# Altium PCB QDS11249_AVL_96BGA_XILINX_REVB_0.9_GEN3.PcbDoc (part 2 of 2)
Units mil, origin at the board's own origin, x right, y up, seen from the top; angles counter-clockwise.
Board outline 3000.03 x 2525.24 mil, 10 copper layers (Top Layer, GND1 - COMMON, INT1, PWR1 - VCC, GND2 - VSS, PWR2 - VCC/VCCIO-EXIT, GND3 - VSSIO, PWR3 - VCCIO, GND4 - COMMON, Bottom Layer), stack 67.702 mil thick; 142 components, 64 nets, 703 pads, 440 vias.
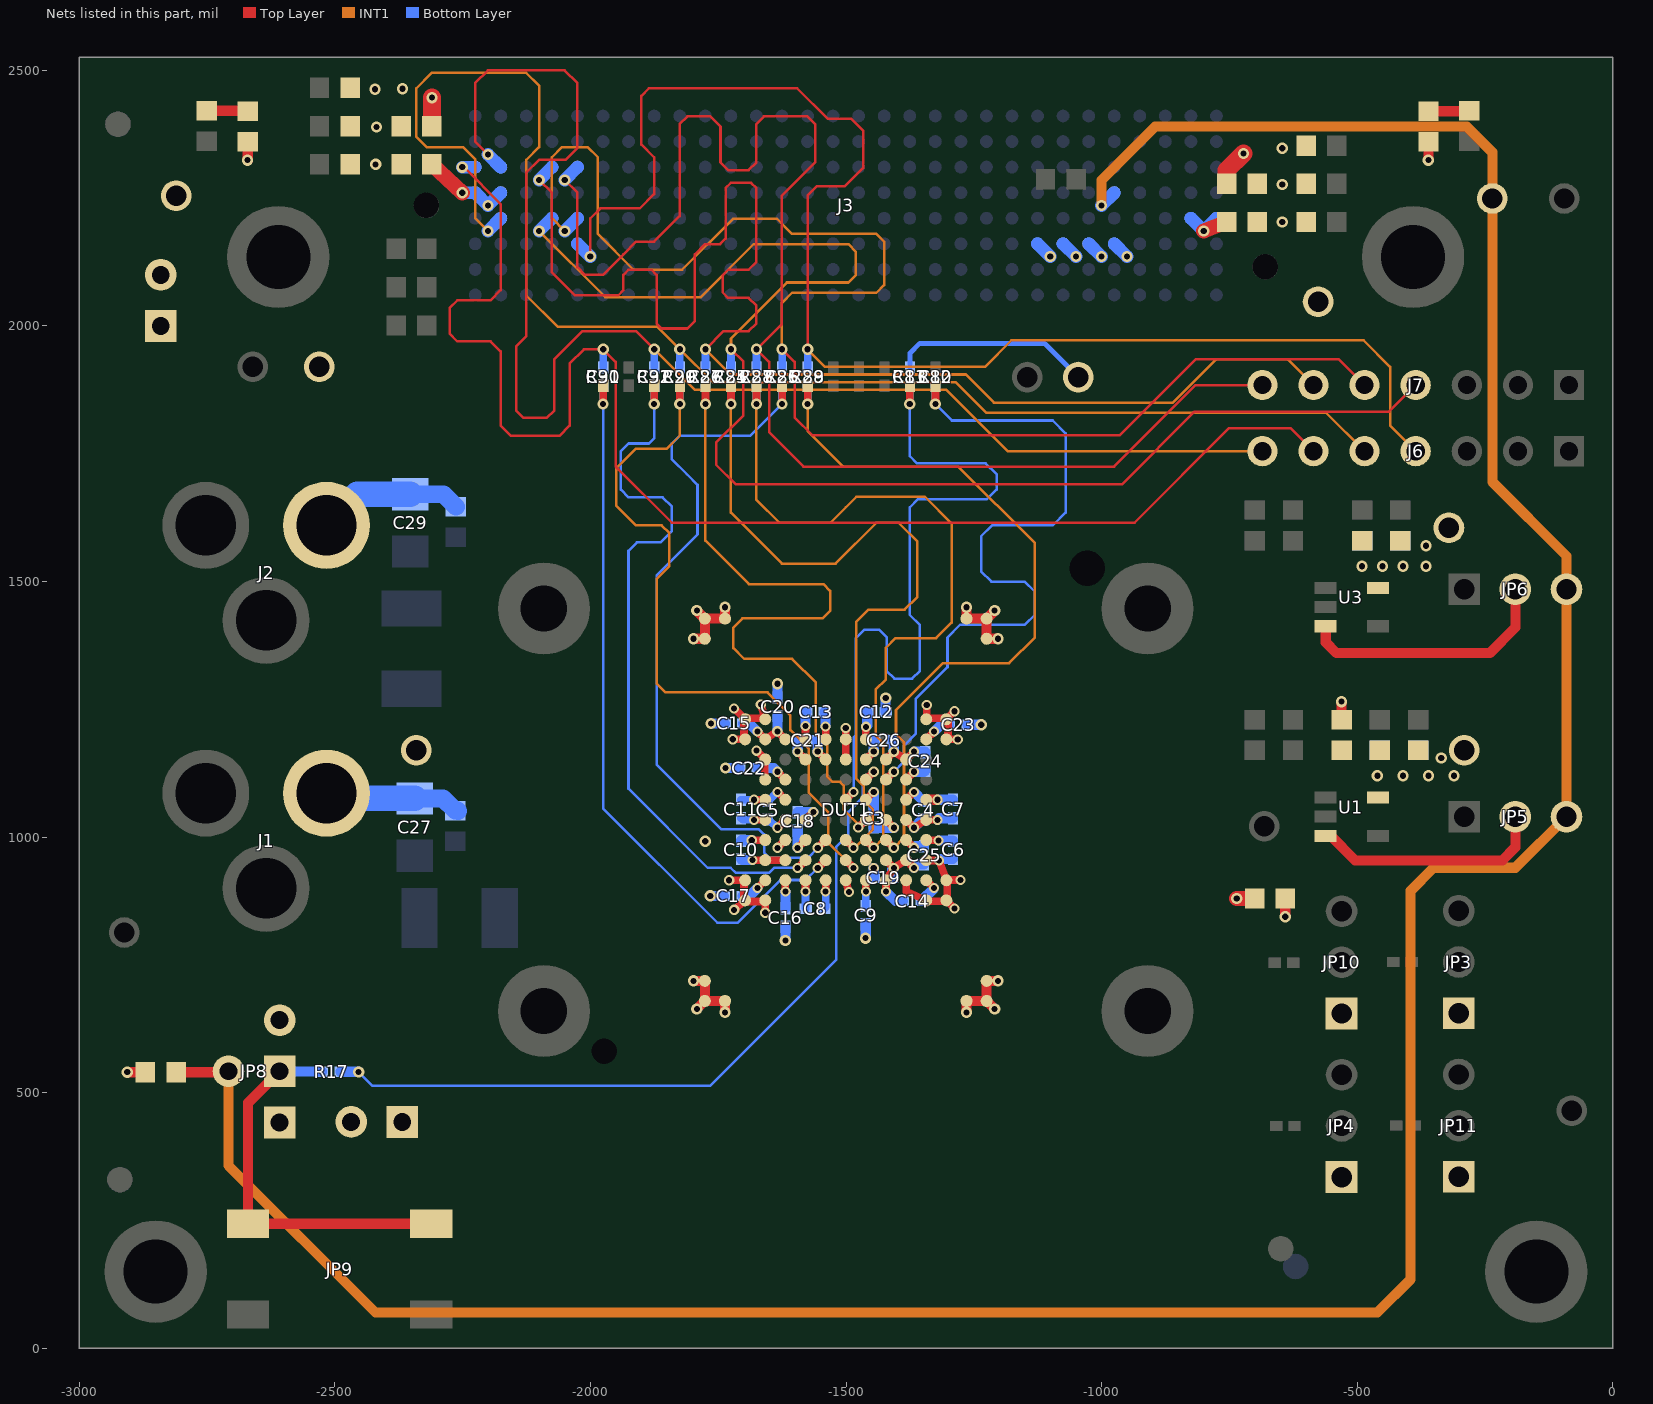
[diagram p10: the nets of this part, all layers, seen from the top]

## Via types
v1: diameter 22, hole 12, Top Layer to Bottom Layer, tented both sides, 368 vias
v2: diameter 20, hole 12, Top Layer to Bottom Layer, tented both sides, 72 vias

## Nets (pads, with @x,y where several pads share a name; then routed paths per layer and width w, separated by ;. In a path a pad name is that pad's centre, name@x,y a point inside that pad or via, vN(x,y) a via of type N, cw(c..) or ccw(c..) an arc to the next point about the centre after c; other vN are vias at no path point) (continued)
INT1#_1: C80.2 DUT1.J10 R12.2 | length 1440.9
  Top Layer w15: DUT1.J10@-1421.76,1112.47 v2(-1406.4,1127.83) ; v1@-1325.02,1847.46 C80.2@-1325.02,1882.86
  Bottom Layer w5: v2(-1406.4,1127.83) -1386.76,1147.47 -1386.76,1178.7 -1363.14,1202.33 -1363.14,1270.72 -1301.5,1332.36 -1301.5,1390.54 -1276.5,1415.54 -1149.92,1415.54 -1130.51,1434.95 -1130.51,1479.95 -1150.51,1499.95 -1215.51,1499.95 -1235.51,1519.95 -1235.51,1588.57 -1214.13,1609.95 -1095.51,1609.95 -1070.51,1634.95 -1070.51,1789.95 -1095.51,1814.95 -1293.01,1814.95 v1(-1325.27,1847.21)
  Bottom Layer w15: v1(-1325.27,1847.21) R12.2@-1325.27,1882.61
INT2#: INT2#.1 R13.1 | length 392.5
  Bottom Layer w10: R13.1@-1375.02,1918.86 -1375.02,1946.45 -1355.51,1965.95 -1111.51,1965.95 INT2#.1@-1045.51,1899.95
INT2#_1: C81.2 DUT1.K8 R13.2 | length 1440.7
  Top Layer w15: DUT1.K8@-1500.5,1073.1 v2(-1485.14,1088.46) ; v1@-1375.02,1847.46 C81.2@-1375.02,1882.86
  Bottom Layer w5: v2(-1485.14,1088.46) -1485.14,1194.9 -1481.24,1198.81 -1481.24,1388.72 -1464.42,1405.54 -1434.8,1405.54 -1420.51,1391.26 -1420.51,1324.95 -1405.51,1309.95 -1370.51,1309.95 -1355.51,1324.95 -1355.51,1414.95 -1375.27,1434.7 -1375.27,1645.2 -1359.33,1661.13 -1224.33,1661.13 -1205.51,1679.95 -1205.51,1709.95 -1226.7,1731.13 -1361.21,1731.13 -1375.27,1745.19 v1(-1375.27,1847.21)
  Bottom Layer w15: v1(-1375.27,1847.21) R13.2@-1375.27,1882.61
IO0: J3.E4 J7.4 R24.1 | length 2877
  Top Layer w5: v1(-1725.02,1954.26) -1700.95,1930.19 -1700.95,1824.95 -1753.99,1771.91 -1753.99,1728.43 -1715.51,1689.95 -1625.51,1689.95 ; -1624.34,1689.95 -960.51,1689.95 -818.12,1832.34 -437.4,1832.34 J7.4@-385.51,1884.22
  INT1 w5: v1(-2100.33,2185.7) -1971.01,2056.38 -1784.09,2056.38 -1680.51,2159.95 -1495.51,2159.95 -1480.51,2144.95 -1480.51,2099.95 -1495.51,2084.95 -1615.51,2084.95 -1725.02,1975.45 v1(-1725.02,1954.26)
  Bottom Layer w15: R24.1@-1725.02,1918.86 v1(-1725.02,1954.26)
  Bottom Layer w25: v1(-2100.33,2185.7) J3.E4@-2075.29,2210.66
IO0_1: C85.2 DUT1.M8 R24.2 | length 1479.7
  Top Layer w15: v1(-1725.02,1847.46) C85.2@-1725.02,1882.86 ; DUT1.M8@-1500.5,994.36 v2(-1485.14,979)
  INT1 w5: v1@-1725.27,1847.46 -1725.27,1634.7 -1625.51,1534.95 -1520.51,1534.95 -1440.51,1614.95 -1396.99,1614.95 -1360.51,1578.48 -1360.51,1469.95 -1385.51,1444.95 -1456.07,1444.95 -1480.02,1421.01 -1480.02,1114.86 -1465.51,1100.36 -1465.51,1071.6 -1447.58,1053.66 -1447.58,1015.21 -1483.79,979 v2(-1485.14,979)
  Bottom Layer w15: v1(-1725.02,1847.46) R24.2@-1725.02,1882.86
IO1: J3.E5 J7.5 R25.1 | length 2876.6
  Top Layer w5: v1(-1625.02,1954.26) -1600.46,1929.7 -1600.46,1820.58 -1566.07,1786.19 -964.28,1786.19 -815.28,1935.19 -536.48,1935.19 J7.5@-485.51,1884.22
  INT1 w5: v1(-2050.29,2185.66) -2075.51,2210.88 -2075.51,2329.95 -2055.51,2349.95 -2005.51,2349.95 -1985.51,2329.95 -1985.51,2179.95 -1915.51,2109.95 -1820.51,2109.95 -1720.51,2209.95 -1635.51,2209.95 -1605.51,2179.95 -1440.51,2179.95 -1425.51,2164.95 -1425.51,2079.95 -1440.51,2064.95 -1605.51,2064.95 -1625.51,2044.95 v1@-1625.51,1954.95 ; v1(-1625.02,1954.26) v1@-1624.92,1954.36
  Bottom Layer w15: R25.1@-1625.02,1918.86 v1(-1625.02,1954.26)
  Bottom Layer w25: v1@-2050.25,2185.62 J3.E5@-2025.25,2210.62
IO1_1: C86.2 DUT1.M7 R25.2 | length 1441.3
  Top Layer w15: v1@-1625.02,1847.46 C86.2@-1625.02,1882.86 ; v2(-1555.24,979) DUT1.M7@-1539.87,994.36
  Bottom Layer w5: v1(-1625.27,1847.21) -1687.52,1784.95 -1825.51,1784.95 -1840.51,1769.95 -1840.51,1738.95 -1811.51,1709.95 -1790.51,1688.95 -1790.51,1591.95 -1870.55,1511.92 -1870.55,1141.99 -1744.24,1015.67 -1670.91,1015.67 -1660.35,1005.12 -1660.35,969.79 -1650.01,959.45 -1574.79,959.45 v2(-1555.24,979)
  Bottom Layer w15: v1(-1625.27,1847.21) R25.2@-1625.27,1882.61
IO2: J3.C4 J7.6 R26.1 | length 2854.2
  Top Layer w5: v1(-2100.24,2285.66) -2075.5,2260.92 -2075.5,2104.94 -2030.51,2059.95 -1945.51,2059.95 -1935.51,2069.95 -1935.51,2099.95 -1925.51,2109.95 -1880.51,2109.95 -1870.51,2099.95 -1870.51,2004.95 -1860.51,1994.95 -1810.51,1994.95 -1795.51,2009.95 -1795.51,2139.95 -1775.51,2159.95 -1746.51,2159.95 -1735.51,2170.95 -1735.51,2269.95 -1725.51,2279.95 -1685.51,2279.95 -1675.51,2269.95 -1675.51,2124.95 -1690.51,2109.95 -1730.51,2109.95 -1741.47,2099 -1741.47,2065.91 -1730.51,2054.95 -1690.51,2054.95 -1675.51,2039.95 -1675.51,2004.95 -1690.51,1989.95 -1739.32,1989.95 v1(-1775.02,1954.26)
  INT1 w5: v1(-1775.02,1954.26) -1725.71,1904.95 -1265.51,1904.95 -1210.51,1849.95 -860.51,1849.95 -775.51,1934.95 -636.24,1934.95 J7.6@-585.51,1884.22
  Bottom Layer w15: R26.1@-1775.02,1918.86 v1(-1775.02,1954.26)
  Bottom Layer w25: v1@-2100.2,2285.62 J3.C4@-2075.2,2310.62
IO2_1: C87.2 DUT1.L9 R26.2 | length 1441
  Top Layer w15: v1(-1775.02,1847.46) C87.2@-1775.02,1882.86 ; v2(-1476.12,1018.75) DUT1.L9@-1460.76,1034.11
  INT1 w5: v1@-1775.27,1847.46 -1775.27,1580.26 -1689.83,1494.83 -1543.89,1494.83 -1530.9,1481.83 -1530.9,1442.54 -1545.59,1427.85 -1702.62,1427.85 -1720.51,1409.95 -1720.51,1369.95 -1699.1,1348.54 -1605.5,1348.54 -1559.02,1302.07 -1559.02,1201.86 -1536.97,1179.81 -1536.97,1118.92 -1526,1107.95 -1511.74,1107.95 -1504.83,1101.05 -1504.83,1092.09 -1504.83,1053.99 v2@-1472.85,1022.01
  Bottom Layer w10: v1(-1775.02,1847.46) R26.2@-1775.02,1882.86
IO3: J3.C5 J7.7 R27.1 | length 2854.1
  Top Layer w5: v1(-2050.24,2285.66) -2025.5,2260.92 -2025.5,2114.94 -2010.51,2099.95 -1975.51,2099.95 -1935.51,2139.95 -1910.51,2164.95 -1875.51,2164.95 -1825.51,2214.95 -1825.51,2394.95 -1810.51,2409.95 -1765.51,2409.95 -1745.51,2389.95 -1745.51,2319.95 -1730.51,2304.95 -1690.51,2304.95 -1675.51,2319.95 -1675.51,2394.95 -1660.51,2409.95 -1575.51,2409.95 -1560.51,2394.95 -1560.51,2319.95 -1625.51,2254.95 -1625.51,2003.76 v1(-1675.02,1954.26) -1650.51,1929.76 -1650.51,1792.21 -1583.26,1724.95 -975.51,1724.95 -816.24,1884.22 J7.7@-685.51,1884.22
  Bottom Layer w15: R27.1@-1675.02,1918.86 v1(-1675.02,1954.26)
  Bottom Layer w25: v1@-2050.2,2285.62 J3.C5@-2025.2,2310.62
IO3_1: C88.2 DUT1.M9 R27.2 | length 1480
  Top Layer w15: v1(-1675.02,1847.46) C88.2@-1675.02,1882.86 ; DUT1.M9@-1461.13,994.36 v2(-1445.77,979)
  INT1 w5: v1@-1675.27,1847.46 -1675.27,1659.7 -1630.51,1614.95 -1530.51,1614.95 -1500.51,1644.95 -1479.62,1665.84 -1345.79,1665.84 -1293.47,1613.52 -1293.47,1419.55 -1323.93,1389.09 -1403.32,1389.09 -1421.96,1370.45 -1421.96,1308.51 -1442.02,1288.45 -1442.02,1198.86 -1426.87,1183.71 -1426.87,997.91 v2(-1445.77,979)
  Bottom Layer w15: v1(-1675.02,1847.46) R27.2@-1675.02,1882.86
IO4: J3.F5 J6.4 R28.1 | length 2854.1
  Top Layer w5: v1(-2000.33,2135.7) -2000.33,2210.14 -1980.51,2229.95 -1903.51,2229.95 -1875.51,2257.95 -1875.51,2329.95 -1900.51,2354.95 -1900.51,2449.95 -1885.51,2464.95 -1595.51,2464.95 -1535.51,2404.95 -1489.51,2404.95 -1466.51,2381.95 -1466.51,2308.95 -1502.51,2272.95 -1557.51,2272.95 -1575.02,2255.45 v1(-1575.02,1954.26)
  INT1 w5: v1(-1575.02,1954.26) -1540.71,1919.95 -1228.51,1919.95 -1176.51,1971.95 -487.51,1971.95 -435.51,1919.95 -435.51,1804.95 J6.4@-385.51,1754.95
  Bottom Layer w15: R28.1@-1575.02,1918.86 v1(-1575.02,1954.26)
  Bottom Layer w25: J3.F5@-2025.29,2160.66 v1(-2000.33,2135.7) v1(-2000.33,2135.7)
IO4_1: C89.2 DUT1.M10 R28.2 | length 1479.8
  Top Layer w15: v1(-1575.02,1847.46) C89.2@-1575.02,1882.86 ; DUT1.M10@-1421.76,994.36 v2(-1406.4,979)
  INT1 w5: v1(-1575.02,1847.46) -1575.02,1794.45 -1505.51,1724.95 -1280.51,1724.95 -1130.51,1574.95 -1130.51,1390.87 -1181.11,1340.27 -1310.19,1340.27 -1402.21,1248.26 -1402.21,1201.65 -1386.54,1185.97 -1386.54,998.87 v2(-1406.4,979)
  Bottom Layer w15: v1(-1575.02,1847.46) R28.2@-1575.02,1882.86
IO5: J3.E2 J6.5 R29.1 | length 2899.4
  INT1 w5: v1(-2200.29,2185.71) -2225.51,2210.94 -2225.51,2326.39 -2249.08,2349.95 -2320.51,2349.95 -2340.51,2369.95 -2340.51,2464.95 -2310.51,2494.95 -2125.51,2494.95 -2100.51,2469.95 -2100.51,2349.95 -2125.51,2324.95 -2125.51,2059.95 -2064.31,1998.75 -1869.51,1998.75 v1(-1825.02,1954.26) -1760.71,1889.95 -1285.51,1889.95 -1225.51,1829.95 -560.51,1829.95 J6.5@-485.51,1754.95
  Bottom Layer w15: R29.1@-1825.02,1918.86 v1(-1825.02,1954.26)
  Bottom Layer w25: v1@-2200.25,2185.68 J3.E2@-2175.25,2210.68
IO5_1: C90.2 DUT1.N8 R29.2 | length 1441
  Top Layer w15: v1(-1825.02,1847.46) C90.2@-1825.02,1882.86 ; DUT1.N8@-1500.5,954.99 v2(-1485.14,939.63)
  INT1 w5: -1870.51,1339.95 -1870.51,1504.95 -1845.51,1529.95 -1845.51,1594.95 -1860.51,1609.95 -1910.51,1609.95 -1949.51,1648.95 -1949.51,1720.95 -1910.51,1759.95 -1850.51,1759.95 -1825.27,1785.2 v1@-1825.27,1847.46 ; -1870.36,1339.95 -1870.36,1300.17 -1853.18,1283 -1653.56,1283 -1608.88,1238.32 -1608.88,1209.41 -1573.02,1173.54 -1573.02,1086.86 -1535.15,1049 -1535.15,989.64 v2@-1488.78,943.27
  Bottom Layer w15: v1(-1825.02,1847.46) R29.2@-1825.02,1882.86
IO6: J3.C1 J6.6 R30.1 | length 2854.1
  Top Layer w5: v1(-2250.75,2310.66) -2247.65,2310.66 -2175.47,2238.47 -2175.47,2069.95 -2195.47,2049.95 -2260.51,2049.95 -2275.51,2034.95 -2275.51,1984.95 -2260.51,1969.95 -2195.51,1969.95 -2175.51,1949.95 -2175.51,1804.95 -2155.51,1784.95 -2060.51,1784.95 -2040.51,1804.95 -2040.51,1926.58 -2012.83,1954.26 v1(-1975.02,1954.26) -1950.51,1929.76 -1950.51,1724.95 -1840.51,1614.95 -935.51,1614.95 -750.51,1799.95 -630.51,1799.95 J6.6@-585.51,1754.95
  Bottom Layer w15: R30.1@-1975.02,1918.86 v1(-1975.02,1954.26)
  Bottom Layer w25: v1@-2250.71,2310.62 -2225.25,2310.62 J3.C1@-2225.21,2310.59
IO6_1: C91.2 DUT1.N7 R30.2 | length 1440.7
  Top Layer w15: v1@-1975.02,1847.46 C91.2@-1975.02,1882.86 ; v2(-1555.24,939.63) DUT1.N7@-1539.87,954.99
  Bottom Layer w5: v1(-1975.27,1847.21) -1975.27,1055.95 -1751.9,832.59 -1711.71,832.59 -1628.25,916.05 -1578.82,916.05 v2(-1555.24,939.63)
  Bottom Layer w15: v1@-1975.02,1847.46 R30.2@-1975.02,1882.86
IO7: J3.C2 J6.7 R31.1 | length 2853.9
  Top Layer w5: v1(-2200.29,2335.61) -2225.51,2360.83 -2225.51,2474.95 -2200.51,2499.95 -2050.51,2499.95 -2025.51,2474.95 -2025.51,2347.83 -2048.39,2324.95 -2100.51,2324.95 -2125.51,2299.95 -2125.51,2259.95 ; -2125.81,2259.95 -2125.81,1979.65 -2145.51,1959.95 -2145.51,1834.95 -2130.51,1819.95 -2085.51,1819.95 -2070.51,1834.95 -2070.51,1934.95 -2015.51,1989.95 -1910.71,1989.95 v1(-1875.02,1954.26)
  INT1 w5: v1(-1875.02,1954.26) -1795.71,1874.95 -1303.82,1874.95 -1183.82,1754.95 J6.7@-685.51,1754.95
  Bottom Layer w15: R31.1@-1875.02,1918.86 v1(-1875.02,1954.26)
  Bottom Layer w25: v1@-2200.25,2335.57 J3.C2@-2175.25,2310.57
IO7_1: C92.2 DUT1.N6 R31.2 | length 1441.2
  Top Layer w15: v1@-1875.02,1847.46 C92.2@-1875.02,1882.86 ; v2(-1594.61,939.63) DUT1.N6@-1579.24,954.99
  Bottom Layer w5: v1(-1875.27,1847.21) -1875.27,1780.2 -1885.51,1769.95 -1925.51,1769.95 -1940.51,1754.95 -1940.51,1679.95 -1925.07,1664.51 -1858.69,1664.51 -1840.51,1646.33 -1840.51,1598.95 -1862.95,1576.51 -1908.95,1576.51 -1925.53,1559.94 -1925.53,1094.97 -1770.51,939.95 -1725.51,939.95 -1715.51,929.95 -1650.51,929.95 -1640.51,939.95 -1594.93,939.95 v2(-1594.61,939.63)
  Bottom Layer w15: v1@-1875.02,1847.46 R31.2@-1875.02,1882.86
MODE0: J3.F23 | length 35.4
  Bottom Layer w25: J3.F23@-1125.29,2160.66 v1(-1100.33,2135.7)
MODE1: J3.F24 | length 35.4
  Bottom Layer w25: J3.F24@-1075.25,2160.62 v1@-1050.25,2135.62
  other v1: -1050.29,2135.66
MODE2: J3.F25 | length 35.4
  Bottom Layer w25: J3.F25@-1025.25,2160.62 v1@-1000.25,2135.62
  other v1: -1000.29,2135.66
MODE3: J3.F26 | length 35.4
  Bottom Layer w25: J3.F26@-975.29,2160.66 v1(-950.33,2135.7)
NetJP5_2: JP5.2 U1.3 | length 461.7
  Top Layer w20: U1.3@-561.69,1002.55 -551.85,1002.55 -503.66,954.36 -216.1,954.36 -190.51,979.95 JP5.2@-190.51,1039.95
NetJP6_2: JP6.2 U3.3 | length 502.1
  Top Layer w20: U3.3@-561.69,1412.55 -561.69,1381.13 -540.51,1359.95 -240.51,1359.95 -190.51,1409.95 JP6.2@-190.51,1479.95
NetLED1_1: LED1.1 R20.2 | length 80.4
  Top Layer w20: LED1.1@-2750.51,2420.95 -2671.51,2420.95 R20.2@-2670.51,2419.95
NetLED2_1: LED2.1 R21.2 | length 80.4
  Top Layer w20: R21.2@-360.51,2419.95 -281.51,2419.95 LED2.1@-280.51,2420.95
PS_POR_B: J3.D26 JP5.3 JP6.3 JP8.4 PS_POR_B.1 R22.1 | length 6145.2
  Top Layer w20: R22.1@-2810.51,539.95 -2709.92,539.95 JP8.4@-2708.02,541.86
  INT1 w20: JP8.4@-2708.02,541.86 -2708.02,357.45 -2420.51,69.95 -460.51,69.95 -395.51,134.95 -395.51,734.95 -395.51,895.19 -350.75,939.95 -190.51,939.95 JP5.3@-90.51,1039.95 -90.51,1351.5 JP6.3@-90.51,1484.95 -90.51,1549.95 -235.51,1694.95 -235.51,2339.95 -285.51,2389.95 -895.51,2389.95 -1000.29,2285.18 v1(-1000.29,2235.71)
  Bottom Layer w25: v1@-1000.25,2235.68 J3.D26@-975.25,2260.68
RESET#: JP8.1 JP9.1 JP9.2 R17.1 | length 765.1
  Top Layer w20: JP8.1@-2608.02,541.86 -2669.65,480.23 JP9.1@-2669.65,243.53 JP9.2@-2311.38,243.53
  Bottom Layer w20: JP8.1@-2608.02,541.86 R17.1@-2525.02,540.86
RESET#_1: DUT1.J9 R17.2 | length 1502.7
  Top Layer w15: DUT1.J9@-1461.13,1112.47 v2(-1445.77,1127.83)
  Bottom Layer w5: v1(-2453.37,540.61) -2426.3,513.54 -1765.92,513.54 -1519.5,759.97 -1519.5,980.97 -1495.51,1004.95 -1495.51,1049.53 -1466.9,1078.14 -1466.9,1106.7 v2(-1445.77,1127.83)
  Bottom Layer w20: R17.2@-2489.02,540.86 v1@-2453.62,540.86
VCC: C3.1 C4.1 C5.1 C6.1 C7.1 C8.1 C9.1 C10.1 C11.1 C12.1 C13.1 C72.1 C73.1 C74.1 DUT1.G7 DUT1.G9 DUT1.K4 DUT1.K5 DUT1.K9 DUT1.K11 DUT1.K12 DUT1.M4 DUT1.M12 DUT1.P7 DUT1.P9 J15.1 JP8.3 R1.2 R5.2 R6.2 R21.1 VCC.1 | length 639.1
  Top Layer w15: v2(-1684.32,993.99) -1658.36,993.99 DUT1.M4@-1657.99,994.36 ; v2(-1680.19,1073.1) DUT1.K4@-1657.99,1073.1 ; v2(-1633.98,1088.46) DUT1.K5@-1618.62,1073.1 ; v2(-1539.95,1216.13) -1539.95,1191.29 DUT1.G7@-1539.87,1191.21 ; v2(-1539.87,893.42) DUT1.P7@-1539.87,915.62 ; v2(-1461.13,893.42) DUT1.P9@-1461.13,915.62 ; DUT1.K9@-1461.13,1073.1 v2(-1445.77,1088.46) ; DUT1.G9@-1461.13,1191.21 v2(-1461.13,1215.74) ; DUT1.K11@-1382.39,1073.1 v2(-1367.03,1088.46) ; DUT1.M12@-1343.02,994.36 -1342.22,993.56 v2(-1319.3,993.56)
  Top Layer w20: DUT1.K12@-1343.02,1073.1 v2(-1320.82,1073.1) ; R1.2@-530.51,1229.95 v1(-530.51,1264.95) ; v1@-360.51,2324.55 R21.1@-360.51,2359.95
  Bottom Layer w15: C11.1@-1705.51,1072.95 -1705.36,1073.1 v2(-1680.19,1073.1) ; C5.1@-1653.01,1070.45 -1651.99,1070.45 v2(-1633.98,1088.46) ; C8.1@-1542.51,859.95 -1539.87,862.59 v2(-1539.87,893.42) ; C9.1@-1461.58,865.29 -1461.58,892.97 v2(-1461.13,893.42)
  Bottom Layer w20: C10.1@-1705.51,992.95 -1704.48,993.99 v2(-1684.32,993.99) ; C13.1@-1541.51,1244.95 -1539.95,1243.39 v2(-1539.95,1216.13) ; v2(-1461.13,1215.74) -1458.51,1218.36 C12.1@-1458.51,1244.95 ; v2(-1445.77,1088.46) -1445.65,1088.34 C3.1@-1445.65,1054.76 ; v2(-1367.03,1088.46) -1349.28,1070.71 C4.1@-1349.02,1070.71 ; v2(-1320.82,1073.1) -1320.67,1072.95 C7.1@-1290.51,1072.95 ; v2(-1319.3,993.56) -1291.12,993.56 C6.1@-1290.51,992.95
  other v1: -646.5,2203.54 -646.5,2276.54 -360.76,2324.3 -646.5,2347.54
VCC_3V3: C32.1 C38.1 C39.1 C40.1 R1.1 U1.5 VCC_3V3.1
  other v1: -460.51,1119.95 -410.51,1119.95 -360.51,1119.95 -310.51,1119.95 -335.51,1154.95
VCC_EXT: C27.1 C28.1 J1.PWR R6.1 VCC_EXT.1 | length 345.3
  Top Layer w35: R6.1@-755.49,2278.29 -755.49,2304.55 v1(-722.5,2337.54)
  Bottom Layer w35: C27.1@-2343.65,1075.67 -2288.27,1075.67 C28.1@-2264.46,1051.86 -2259.54,1051.86 C28.1@-2258.54,1050.86
  Bottom Layer w50: J1.PWR@-2516.46,1085.86 -2506.27,1075.67 C27.1@-2343.65,1075.67
VCC_INT: J3.E29 J3.E30 R5.1 | length 118.8
  Top Layer w30: v1(-800.29,2185.71) R5.1@-755.49,2203.29
  Bottom Layer w25: J3.E29@-825.25,2210.68 v1(-800.29,2185.71) -800.25,2185.68 J3.E30@-775.29,2210.64
VCCIO: C14.1 C15.1 C16.1 C17.1 C18.1 C19.1 C20.1 C21.1 C22.1 C23.1 C24.1 C25.1 C26.1 C69.1 C70.1 C71.1 DUT1.G4 DUT1.G5 DUT1.G12 DUT1.H7 DUT1.H9 DUT1.J5 DUT1.J11 DUT1.M6 DUT1.M11 DUT1.N9 DUT1.P4 DUT1.P5 DUT1.P12 J15.2 JP3.1 JP4.1 JP7.2 JP8.2 JP10.1 JP11.1 R3.2 R4.2 R7.2 R20.1 VCCIO.1 | length 749.6
  Top Layer w15: v2(-1673.35,900.26) DUT1.P4@-1657.99,915.62 ; v2(-1673.35,1206.57) DUT1.G4@-1657.99,1191.21 v2(-1634.32,1206.91) DUT1.G5@-1618.62,1191.21 ; v2(-1633.98,1127.83) DUT1.J5@-1618.62,1112.47 ; v2(-1618.62,893.42) DUT1.P5@-1618.62,915.62 ; v2(-1594.61,979) DUT1.M6@-1579.24,994.36 ; v2(-1555.24,1167.2) DUT1.H7@-1539.87,1151.84 ; DUT1.H9@-1461.13,1151.84 v2(-1445.77,1167.2) ; DUT1.M11@-1382.39,994.36 v2(-1367.03,979) ; DUT1.J11@-1382.39,1112.47 v2(-1367.03,1127.83) ; DUT1.P12@-1343.02,915.62 v2(-1327.66,900.26) ; DUT1.G12@-1343.02,1191.21 v2(-1327.66,1206.57)
  Top Layer w20: v1@-2670.51,2324.55 R20.1@-2670.51,2359.95 ; v1(-640.76,844.3) R7.2@-640.76,879.7
  Bottom Layer w20: C17.1@-1702.51,884.95 -1688.65,884.95 v2(-1673.35,900.26) ; C15.1@-1701.29,1222.32 -1689.09,1222.32 v2(-1673.35,1206.57) ; C22.1@-1672.51,1134.95 -1641.09,1134.95 v2(-1633.98,1127.83) ; v2(-1634.32,1206.91) -1634.01,1207.22 C20.1@-1634.01,1236.95 ; v2(-1618.62,893.42) -1618.62,860.68 C16.1@-1618.5,860.68 ; v2(-1594.61,979) C18.1@-1594.61,1012.55 ; C21.1@-1556.51,1189.95 -1555.24,1188.67 v2(-1555.24,1167.2) ; v2(-1445.77,1167.2) -1445.77,1188.69 C26.1@-1444.51,1189.95 ; C19.1@-1445.58,920.14 -1445.77,920.34 v2(-1445.77,939.63) v2@-1445.58,939.43 ; v2(-1367.03,979) -1363.72,982.31 C25.1@-1347.29,982.31 ; v2(-1367.03,1127.83) -1347.25,1127.83 C24.1@-1345.03,1130.06 ; C14.1@-1352.51,874.95 -1352.51,875.41 v2(-1327.66,900.26) ; v2(-1327.66,1206.57) -1314.28,1219.95 C23.1@-1298.51,1219.95
  other v1: -2420.13,2316.06 -2670.76,2324.3 -2418.62,2389.01 -2421.44,2463.12 -2367.47,2463.92
VCCIO_1V8: C36.1 C48.1 C49.1 C50.1 R7.1 U3.5 VCCIO_1V8.1 | length 35
  Top Layer w30: v1(-735.51,879.95) R7.1@-700.51,879.95
  other v1: -490.51,1529.95 -450.51,1529.95 -410.51,1529.95 -365.51,1529.95 -365.51,1569.95
VCCIO_EXT: C29.1 C30.1 J2.PWR JP7.1 R4.1 R22.2 VCCIO_EXT.1 | length 379.7
  Top Layer w20: v1@-2905.91,539.95 R22.2@-2870.51,539.95
  Top Layer w35: R4.1@-2310.02,2390.86 v1(-2310.03,2446.6)
  Bottom Layer w35: C29.1@-2352.5,1670.76 -2287.63,1670.76 C30.1@-2263.23,1646.35
  Bottom Layer w50: J2.PWR@-2516.46,1609.95 -2455.65,1670.76 C29.1@-2352.5,1670.76
  other v1: -2906.16,540.2
VCCIO_INT: J3.D1 J3.D2 R3.1 | length 177.2
  Top Layer w30: R3.1@-2310.02,2315.86 v1(-2250.75,2260.66)
  Bottom Layer w25: v1@-2250.71,2260.62 -2225.25,2260.62 J3.D1@-2225.21,2260.59 ; J3.D1@-2225.29,2260.66 v1(-2200.32,2235.71) -2200.25,2235.68 J3.D2@-2175.25,2260.68
VSS: C3.2 C4.2 C5.2 C6.2 C7.2 C8.2 C9.2 C10.2 C11.2 C12.2 C13.2 DUT1.A1 DUT1.A2 DUT1.A14 DUT1.A15 DUT1.B1 DUT1.B15 DUT1.F3 DUT1.F4 DUT1.F12 DUT1.F13 DUT1.G3 DUT1.G6 DUT1.G8 DUT1.G13 DUT1.H4 DUT1.H8 DUT1.J4 DUT1.L4 DUT1.L5 DUT1.L10 DUT1.L11 DUT1.L12 DUT1.N4 DUT1.N5 DUT1.N12 DUT1.P3 DUT1.P6 DUT1.P11 DUT1.P13 DUT1.R3 DUT1.R4 DUT1.R12 DUT1.R13 DUT1.W1 DUT1.W15 DUT1.Y1 DUT1.Y2 DUT1.Y14 DUT1.Y15 | length 2025.4
  Top Layer w15: v2(-1728.56,915.62) DUT1.P3@-1697.36,915.62 -1699.42,913.56 -1699.42,878.31 DUT1.R3@-1697.36,876.25 ; v2(-1721.57,1191.37) -1697.52,1191.37 DUT1.G3@-1697.36,1191.21 -1699.46,1193.31 -1699.46,1228.48 DUT1.F3@-1697.36,1230.58 ; v2(-1718.97,1251.85) -1718.62,1251.85 DUT1.F3@-1697.36,1230.58 ; v2(-1718.82,857.73) DUT1.R3@-1697.36,876.25 ; DUT1.R3@-1699.18,876.25 DUT1.R3@-1697.36,876.25 ; v2(-1683.19,954.99) DUT1.N4@-1657.99,954.99 DUT1.N5@-1618.62,954.99 ; v2(-1680.19,1033.73) DUT1.L4@-1657.99,1033.73 ; v2(-1674.99,1169.08) DUT1.H4@-1657.99,1152.07 ; v2@-1666.65,1259.13 v2(-1666.65,1259.64) DUT1.F4@-1657.99,1230.58 -1659.78,1232.38 -1695.56,1232.38 DUT1.F3@-1697.36,1230.58 ; DUT1.J4@-1657.99,1112.47 -1659.07,1113.55 -1659.07,1150.76 DUT1.H4@-1657.99,1151.84 ; v2(-1657.91,852.03) -1657.91,876.18 DUT1.R4@-1657.99,876.25 -1660.08,874.16 -1695.26,874.16 DUT1.R3@-1697.36,876.25 ; v2(-1633.98,1018.37) DUT1.L5@-1618.62,1033.73 ; v2(-1579.24,893.42) DUT1.P6@-1579.24,915.62 ; DUT1.G6@-1579.24,1191.21 -1579.12,1191.33 v2(-1579.12,1217.16) ; DUT1.H8@-1500.5,1151.84 DUT1.G8@-1500.5,1191.21 v2(-1500.5,1213.42) ; DUT1.L10@-1421.76,1033.73 v2(-1406.4,1018.37) ; DUT1.P11@-1382.39,915.62 -1382.39,893.42 DUT1.R12@-1343.02,876.25 ; DUT1.L11@-1382.39,1033.73 v2(-1367.03,1018.37) DUT1.L12@-1343.02,1033.73 v2(-1320.82,1033.73) ; DUT1.N12@-1343.02,954.99 -1342.2,954.17 v2(-1318.01,954.17) DUT1.P13@-1303.65,915.62 ; v2(-1342.02,1258.65) -1342.02,1231.59 DUT1.F12@-1343.02,1230.58 -1340.93,1232.68 -1305.75,1232.68 DUT1.F13@-1303.65,1230.58 ; DUT1.R12@-1341.05,874.28 -1305.63,874.28 DUT1.R13@-1303.65,876.25 ; v2(-1287.95,860.55) DUT1.R13@-1303.65,876.25 ; v2(-1287.95,1246.28) DUT1.F13@-1303.65,1230.58 ; v2(-1281.45,1191.21) DUT1.G13@-1303.65,1191.21 -1300.63,1194.23 -1300.63,1227.56 DUT1.F13@-1303.65,1230.58 ; v2(-1276.03,916.01) -1303.26,916.01 DUT1.P13@-1303.65,915.62 ; DUT1.R13@-1303.65,876.25 -1302.1,877.81 -1302.1,914.06 DUT1.P13@-1303.65,915.62
  Top Layer w20: v1(-1798.3,718.77) DUT1.W1@-1776.1,718.77 DUT1.Y1@-1776.1,679.4 ; v1(-1798.3,1388.06) DUT1.B1@-1776.1,1388.06 DUT1.A1@-1776.1,1427.43 ; v1(-1791.8,663.7) DUT1.Y1@-1776.1,679.4 ; v1(-1791.8,1443.13) DUT1.A1@-1776.1,1427.43 ; v1(-1736.73,657.2) DUT1.Y2@-1736.73,679.4 DUT1.Y1@-1776.1,679.4 ; v1(-1736.73,1449.64) DUT1.A2@-1736.73,1427.43 DUT1.A1@-1776.1,1427.43 ; v1(-1264.28,657.2) DUT1.Y14@-1264.28,679.4 DUT1.Y15@-1224.91,679.4 ; v1(-1264.28,1449.64) DUT1.A14@-1264.28,1427.43 DUT1.A15@-1224.91,1427.43 ; v1(-1209.21,663.7) DUT1.Y15@-1224.91,679.4 ; v1(-1209.21,1443.13) DUT1.A15@-1224.91,1427.43 ; v1(-1202.71,718.77) DUT1.W15@-1224.91,718.77 DUT1.Y15@-1224.91,679.4 ; v1(-1202.71,1388.06) DUT1.B15@-1224.91,1388.06 DUT1.A15@-1224.91,1427.43
  Bottom Layer w15: C11.2@-1705.51,1036.95 -1702.29,1033.73 v2(-1680.19,1033.73) ; C5.2@-1653.01,1034.45 v2(-1633.98,1018.37) ; v2(-1579.24,893.42) -1579.24,860.68 C8.2@-1578.51,859.95
  Bottom Layer w20: C10.2@-1705.51,956.95 -1703.55,954.99 v2(-1683.19,954.99) ; v2(-1579.12,1217.16) -1579.12,1243.34 C13.2@-1577.51,1244.95 ; v1(-1461.75,802.29) -1461.58,802.47 C9.2@-1461.58,829.29 ; C3.2@-1445.65,1018.76 -1445.26,1018.37 v2(-1406.4,1018.37) ; C12.2@-1422.51,1244.95 -1422.51,1271.78 v1(-1422.34,1271.95) ; v2(-1367.03,1018.37) -1350.7,1034.71 C4.2@-1349.02,1034.71 ; v2(-1320.82,1033.73) -1317.6,1036.95 C7.2@-1290.51,1036.95 ; v2(-1318.01,954.17) -1315.23,956.95 C6.2@-1290.51,956.95
  other v1: -1775.37,991.9
VSSIO: C14.2 C15.2 C16.2 C17.2 C18.2 C19.2 C20.2 C21.2 C22.2 C23.2 C24.2 C25.2 C26.2 DUT1.H6 DUT1.H10 DUT1.H11 DUT1.L6 DUT1.M5 DUT1.N10 DUT1.N11 DUT1.P8 DUT1.P10 | length 631.1
  Top Layer w15: v2(-1633.98,979) DUT1.M5@-1618.62,994.36 ; v2(-1594.61,1167.2) DUT1.H6@-1579.24,1151.84 ; DUT1.L6@-1579.24,1033.73 v2(-1563.88,1049.09) ; DUT1.P8@-1500.5,915.62 v2(-1494.31,892.42) ; v2(-1421.76,893.42) DUT1.P10@-1421.76,915.62 v2(-1406.4,939.63) ; DUT1.N10@-1421.76,954.99 v2(-1406.4,939.63) ; DUT1.H10@-1421.76,1151.84 v2(-1406.4,1167.2) DUT1.H11@-1382.39,1151.84 v2(-1367.03,1167.2) ; v2(-1367.03,939.63) DUT1.N11@-1382.39,954.99 v2(-1406.4,939.63)
  Bottom Layer w20: v1(-1765.52,885.13) -1765.34,884.95 C17.2@-1738.51,884.95 ; v1(-1764.29,1222.49) -1764.11,1222.32 C15.2@-1737.29,1222.32 ; v1(-1735.52,1135.13) -1735.34,1134.95 C22.2@-1708.51,1134.95 ; C20.2@-1634.01,1272.95 -1634.01,1299.78 v1(-1633.84,1299.95) ; v1(-1618.67,797.68) -1618.5,797.86 C16.2@-1618.5,824.68 ; C18.2@-1594.61,1048.55 -1594.06,1049.09 v2(-1563.88,1049.09) ; v2(-1594.61,1167.2) -1594.61,1187.86 C21.2@-1592.51,1189.95 ; v2(-1421.76,893.42) -1403.3,874.95 C14.2@-1388.51,874.95 ; C19.2@-1409.58,920.14 -1409.58,936.46 v2(-1406.4,939.63) ; C26.2@-1408.51,1189.95 -1406.4,1187.84 v2(-1406.4,1167.2) ; v2(-1367.03,939.63) -1360.35,946.31 C25.2@-1347.29,946.31 ; v2(-1367.03,1167.2) -1346.17,1167.2 C24.2@-1345.03,1166.06 ; C23.2@-1262.51,1219.95 -1235.69,1219.95 v1(-1235.51,1219.78)
pads on no net: C3. C4. C5. C6. C7. C8. C9. C10. C11. C12. C13. C14. C15. C16. C17. C18. C19. C20. C21. C22. C23. C24. C25. C26. C27.ORIGIN C29.ORIGIN C78. C79. C80. C81. C82. C83. C85. C86. C87. C88. C89. C90. C91. C92. C93. C94. C95. C96. DUT1.GUIDEPIN_1.55_NP DUT1.GUIDEPIN_2.05_NP DUT1.H5 DUT1.HOLE2.3 DUT1.J6 DUT1.J7 DUT1.K10 DUT1.L8 DUT1.ORIGIN FUDICIAL1.FUDICIAL FUDICIAL2.FUDICIAL FUDICIAL3.FUDICIAL FUDICIAL4.FUDICIAL FUDICIAL5.FUDICIAL FUDICIAL6.FUDICIAL J3. J3.A1 J3.A2 J3.A5 J3.A6 J3.A9 J3.A10 J3.A13 J3.A14 J3.A17 J3.A18 J3.A21 J3.A22 J3.A25 J3.A26 J3.A29 J3.A30 J3.B3 J3.B4 J3.B7 J3.B8 J3.B11 J3.B12 J3.B15 J3.B16 J3.B19 J3.B20 J3.B23 J3.B24 J3.B27 J3.B28 J3.B29 J3.B30 J3.C7 J3.C8 J3.C10 J3.C11 J3.C13 J3.C14 J3.C16 J3.C17 J3.C19 J3.C20 J3.C22 J3.C23 J3.C25 J3.C26 J3.C29 J3.C30 J3.D5 J3.D8 J3.D9 J3.D11 J3.D12 J3.D14 J3.D15 J3.D17 J3.D18 J3.D20 J3.D21 J3.D27 J3.D28 J3.D30 J3.E7 J3.E8 J3.E10 J3.E11 J3.E13 J3.E14 J3.E16 J3.E17 J3.E19 J3.E20 J3.E22 J3.E23 J3.E25 J3.E26 J3.F9 J3.F11 J3.F12 J3.F14 J3.F15 J3.F17 J3.F18 J3.F20 J3.F21 J3.F27 J3.F28 J3.F29 J3.F30 J3.G1 J3.G3 J3.G4 J3.G6 J3.G7 J3.G9 J3.G10 J3.G12 J3.G13 J3.G15 J3.G16 J3.G18 J3.G19 J3.G21 J3.G22 J3.G24 J3.G25 J3.G26 J3.G27 J3.G29 J3.G30 J3.H1 J3.H2 J3.H5 J3.H6 J3.H8 J3.H9 J3.H11 J3.H12 J3.H14 J3.H15 J3.H17 J3.H18 J3.H20 J3.H21 J3.H23 J3.H24 J3.H25 J3.H26 J3.H28 J3.H29 J3.H30 R10. R11. R12. R13. R14. R15. R17. R24. R25. R26. R27. R28. R29. R30. R31. R32. R33. R34. R35. U1. U1.4 U3. U3.4

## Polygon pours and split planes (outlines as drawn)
GND on PWR2 - VCC/VCCIO-EXIT "GND_L06_P027" (solid, remove dead copper, pour order 27): -805.51,1974.95 -1860.51,1974.95 -1860.51,-0.05 -0.51,-0.05 -0.51,794.95 -805.51,794.95 -805.51,1964.95
VCCIO_EXT on PWR2 - VCC/VCCIO-EXIT "NONET_L-01_P-001" (solid, remove dead copper, pour order 9): -2110.51,2524.86 -2110.51,2314.95 -2330.51,2094.95 -2330.51,1589.95 -2635.59,1284.88 -2635.59,591.33 -1870.51,591.33 -1870.51,-0.01 -3000.02,-0.01 -3000.02,541.86 -3000.01,2226.24 -3000.01,2524.86
VCC_EXT on PWR2 - VCC/VCCIO-EXIT "NONET_L-01_P-001" (solid, remove dead copper, pour order 3): -2106.91,2525.08 -2106.91,2311.37 -2320.51,2097.66 -2320.51,1579.95 -2624.27,1276.2 -2624.27,597.65 -1870.51,597.65 -1870.51,1979.95 -0.02,1979.95 -0.02,2524.98 -1043.02,2524.98 -1836.77,2525.08
VCCIO_1V8 on PWR2 - VCC/VCCIO-EXIT "NONET_L-01_P-001" (solid, remove dead copper, pour order 26): -795.51,808.18 -792.29,804.95 -1.29,804.95 -0.02,803.67 -0.02,1974.95 -795.51,1974.95
VCCIO on PWR3 - VCCIO "NONET_L-01_P-001" (solid, remove dead copper, pour order 25): -3000.02,-0.01 -0.02,-0.01 -0.02,529.95 -0.02,1449.95 -0.02,2524.86 -3000.01,2524.86 -3000.01,1968.21
+5V on PWR3 - VCCIO "NONET_L-01_P-001" (solid, remove dead copper, pour order 22): -10.51,989.95 -790.51,989.95 -790.51,2049.95 -2290.51,2049.95 -2290.51,2525.22 -10.51,2525.22
VCC on PWR1 - VCC "NONET_L-01_P-001" (solid, remove dead copper, pour order 4): -0.02,2525.22 -0.02,1274.86 -0.02,70.86 -0.02,30.56 -0.02,-0.01 -3000.02,-0.01 -3000.02,2525.21 -674.34,2525.22
GND on GND1 - COMMON "NONET_L-01_P-001" (solid, remove dead copper, pour order 11): -3000.02,2525.22 -0.02,2525.22 -0.02,16.13 -3000.02,16.13
GND on Top Layer "NONET_L-01_P-001" (solid, remove dead copper, pour order 21): -3000.02,2525.22 -0.02,2525.22 -0.02,16.13 -3000.02,16.13
GND on GND4 - COMMON "NONET_L-01_P-001" (solid, remove dead copper, pour order 17): -3000.02,2525.22 -0.02,2525.22 -0.02,-0.01 -3000.02,-0.01
GND on INT1 "NONET_L-01_P-001" (solid, remove dead copper, pour order 19): -3000.02,2525.22 -0.02,2525.22 -0.02,16.13 -3000.02,16.13
VSS on GND2 - VSS "VSS_L05_P028" (solid, remove dead copper, pour order 28): -3000.02,2525.23 -3000.02,-0.01 0,-0.01 0,2525.22 -2963.56,2525.22
VSSIO on GND3 - VSSIO "VSSIO_L07_P029" (solid, remove dead copper, pour order 29): -3000.01,2524.86 -3000.01,-0.01 -0.02,-0.01 -0.02,2525.22 -2963.56,2525.22
GND on Bottom Layer "GND_L10_P030" (solid, remove dead copper, pour order 30): -3000.02,2525.22 -3000.02,-0.01 0,-0.01 0,2525.22 -2938.84,2525.22

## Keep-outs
Keep-Out Layer:
  circle w3: c-909.95,1447.12 r94.34
  circle w5: c-2091.06,659.72 r101.29
  circle w5: c-909.95,659.72 r101.29
  circle w5: c-2091.06,1447.12 r101.29
  lines w5: -2498.73,2133.86 cw(c-2610.57,2134.86) -2498.72,2134.86 ; -278.73,2133.86 cw(c-390.57,2134.86) -278.72,2134.86
  lines w10: -2735.37,148.31 cw(c-2850.51,149.95) -2735.36,149.95 ; -264.68,148.3 ccw(c-149.53,149.94) -264.69,149.94
  lines w40: -0.02,-0.01 -3000.03,-0.01 -3000.01,2524.86 -0.02,2524.86 ; -0.02,0 -0.02,-0.01 ; -0.02,0 -0.02,2524.86 ; -0.02,2524.86 -0.02,2524.86

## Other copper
Top Layer:
  region net VCC: -578.5,2177.36 -578.5,2300.69 -716.76,2300.69 -716.76,2177.36
  rectangle net GND: -2459.02,1977.86 -2361.02,2170.86
  rectangle net GND: -2605.02,2295.86 -2511.02,2487.86
  rectangle net VCCIO: -2489.02,2295.86 -2348.02,2485.86
  rectangle net GND: -559,2266.86 -457.02,2372.11
  rectangle net GND: -559,2183.29 -521,2372.11
  rectangle net VCC: -678.68,2183.29 -578.86,2384.11
  region net VCC_3V3: -550.51,1188.95 -346.51,1188.95 -315.51,1219.95 -245.51,1219.95 -245.51,1164.95 -344.92,1065.54 -480.99,1065.54 -480.99,1075.42 -550.51,1144.95
  region net +5V: -540.04,1065.54 -750.51,1065.54 -750.51,1188.95 -575.51,1188.95 -575.51,1139.95 -540.04,1104.48
  region net VCCIO_1V8: -510.51,1598.95 -391.51,1598.95 -340.51,1649.95 -270.51,1649.95 -270.51,1584.95 -325.51,1529.95 -379.92,1475.54 -510.51,1475.54
  region net +5V: -540.04,1475.54 -540.04,1598.95 -750.51,1598.95 -750.51,1475.54
  pour cut-out: -737.81,1841.41 -728.81,1850.41 -728.81,1866.41 -743.09,1880.69 -719.74,1880.69 -709.3,1870.25 -709.3,1845.86 -713.74,1841.41
  pour cut-out: -737.81,1891.97 -728.81,1900.97 -728.81,1916.97 -743.09,1931.25 -719.74,1931.25 -709.3,1920.8 -709.3,1896.41 -713.74,1891.97
  pour cut-out: -1555.76,1833.2 -1564.76,1824.2 -1564.76,1808.2 -1550.48,1793.92 -1573.82,1793.92 -1584.27,1804.37 -1584.27,1828.76 -1579.82,1833.2
  pour cut-out: -2698.01,2383.67 -2644.01,2383.67 -2644.01,2398.67 -2698.01,2398.67
  pour cut-out: -387.51,2383.17 -333.51,2383.17 -333.51,2398.17 -387.51,2398.17
  pour cut-out: -1994.77,1905.11 -1994.77,1828.55 -1304.77,1828.55 -1304.77,1905.11
  pour cut-out: -784.49,2233.29 -726.96,2233.29 -726.96,2248.29 -784.49,2248.29
  pour cut-out: -2281.02,2345.86 -2281.02,2360.86 -2337.82,2360.86 -2337.82,2345.86
  text "TOP" at 818.9,847.46 h65
PWR2 - VCC/VCCIO-EXIT:
  text "PWR2" at 818.9,246.82 h65
GND1 - COMMON:
  text "GND1" at 2142.32,710.46 h65
INT1:
  pour cut-out: -1780.51,1952.45 -1818.01,1952.45 -1818.01,1959.95 -1780.51,1959.95
  pour cut-out: -1880.51,1989.95 -1880.51,1959.95 -1865.51,1959.95 -1865.51,1989.95
  pour cut-out: -1570.51,1967.45 -1528.01,1967.45 -1528.01,1919.95
  pour cut-out: -1615.99,1198.49 -1604.51,1187.02 -1604.51,1110.64 -1619.52,1095.64 -1619.52,1082.1 -1606.6,1069.18 -1573.02,1102.77 -1573.02,1173.54 -1601.34,1201.86
  pour cut-out: -1546.28,1302.07 -1546.28,1285.71 -1531.51,1270.95 -1498.51,1270.95 -1490.51,1278.95 -1480.02,1268.45 -1480.02,1135.45 -1496.51,1118.95 -1521.41,1118.95 -1531.02,1128.56 -1531.02,1173.86 -1559.02,1201.86 -1559.02,1287.2
  pour cut-out: -1594.51,1239.95 -1570.51,1263.95 -1559.02,1252.46 -1559.02,1214.61 -1571.77,1201.86 -1601.34,1201.86 -1608.88,1209.41 -1608.88,1239.95
  pour cut-out: -1480.02,1315.23 -1459.32,1294.54 -1442.54,1294.54 -1427.27,1309.81 -1427.27,1239.53 -1442.02,1224.79 -1470.77,1224.79 -1480.02,1234.03
  text "INTERNAL1" at 818.9,699.46 h65
PWR1 - VCC:
  text "PWR1" at 818.9,543.46 h65
GND2 - VSS:
  text "GND2" at 2142.32,546.46 h65
PWR3 - VCCIO:
  text "PWR3" at 818.9,390.36 h65
GND3 - VSSIO:
  text "GND3" at 2137.32,400.46 h65
GND4 - COMMON:
  text "GND4" at 2137.32,236.46 h65
Bottom Layer:
  region net GND: -2415.61,1340.34 -2415.61,1224.7 -2275.61,1224.7 -2275.61,1340.34
  rectangle net GND: -2212.96,771.86 -2068.32,911.86
  region net VCCIO_1V8: -510.51,1474.95 -380.51,1474.95 -270.51,1584.95 -270.51,1649.95 -340.51,1649.95 -391.51,1598.95 -510.51,1598.95
  region net +5V: -750.51,1598.95 -540.51,1598.95 -540.51,1474.95 -750.51,1474.95
  region net VCC_3V3: -490.51,1188.95 -346.51,1188.95 -315.51,1219.95 -245.51,1219.95 -245.51,1094.95 -490.51,1094.95
  region net +5V: -750.51,1188.95 -575.51,1188.95 -575.51,1064.95 -750.51,1064.95
  pour cut-out: -1995.02,1838.54 -1305.02,1838.54 -1305.02,1959.66 -1995.02,1959.66
  text "BOTTOM" at 2142.32,849.46 h65

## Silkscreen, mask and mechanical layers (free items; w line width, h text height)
Top Overlay:
  drawing of 1950 lines, arcs and shapes, not listed
  text "IO7" at -2222.67,2447.39 h60 r270
  text "IO6" at -2270.54,2417.89 h60 r270
  text "IO2" at -2119.71,2392.43 h60 r270
  text "IO3" at -2068.72,2392.59 h60 r270
  text "CS1#" at -1917.31,2267.49 h35
  text "VCCIO" at -2955.78,2210.32 h40 r270
  text "CLK2" at -2271.92,2176.51 h60 r270
  text "CS2#" at -1917.5,2169.21 h35
  text "IO5" at -2221.46,2151.56 h60 r270
  text "IO0" at -2121.5,2151.54 h60 r270
  text "IO1" at -2066.5,2151.54 h60 r270
  text "CS2#" at -948.34,2124.95 h35 r270
  text "CLK1" at -1811.5,2117.54 h35
  text "IO4" at -1968.5,2115.54 h35
  text "CLK2" at -853.34,2114.95 h35 r270
  text "GND" at -903.34,2089.95 h35 r270
  text "IO7" at -1133.34,2064.95 h35 r270
  text "IO6" at -1088.34,2064.95 h35 r270
  text "IO5" at -1043.34,2064.95 h35 r270
  text "IO4" at -998.34,2064.95 h35 r270
  text "VCC" at -2956.63,2023.15 h40 r270
  text "CS1#" at -361.62,1954.52 h35
  text "IO3" at -731.69,1951.81 h35
  text "IO2" at -631.69,1951.81 h35
  text "IO1" at -531.69,1951.81 h35
  text "IO0" at -450.11,1952.02 h35
  text "GND" at -231.69,1951.81 h35
  text "CLK1" at -117.68,1951.63 h35
  text "+5V" at -285.51,1359.95 h35
  text "EN" at -280.51,1304.95 h35
  text "PS_POR_B" at -280.51,1249.95 h35
  text "+5V" at -395.51,1089.95 h35 r270
  text "PS_POR_B" at -98.15,959.95 h35 r270
  text "EN" at -216.1,954.36 h35 r270
  text "HBP0" at -230.51,799.95 h35 r270
  text "HBP2" at -717.14,789.92 h35
  text "VCCIO_EXIT" at -2385.51,774.95 h35 r270
  text "VCC" at -2660.51,719.95 h35
  text "RESET#" at -2530.51,699.95 h35 r270
  text "VCCIO" at -2465.51,654.95 h35 r270
  text "HTBSEL" at -230.51,529.95 h35 r270
  text "HBP1" at -712.14,469.92 h35
  text "PS_POR_B" at -2970.51,409.95 h35
  text "VCCIO" at -2630.51,329.95 h35
  text "PN: 96BGA XILINX (B) GEN3" at -1468.51,44.45 h45
  text "TOP SILKSCREEN" at 818.9,-56.54 h65
Bottom Overlay:
  region: -941.51,399.95 -1629.01,399.95 -1629.01,152.95 -941.51,152.95
  lines w6: -2970.51,394.95 -2705.51,394.95 -2705.51,479.95 ; -2605.51,264.95 -2605.51,379.95 ; -310.51,1409.95 -30.51,1409.95 -30.51,1224.95 -310.51,1224.95 -310.51,1434.95 ; -2680.51,34.95 -2450.51,34.95 -2450.51,264.95 -2680.51,264.95 -2680.51,34.95 ; -1179.94,1714.95 -1179.94,1789.95 -754.94,1789.95 -754.94,1714.95 -1179.94,1714.95
  text "VCCIO" at -2748.5,2319.54 h35
  text "GND1" at -40.51,2309.95 h35
  text "VCC" at -528.96,2108.48 h35
  text "VCCIO" at -2954.92,2064.34 h40 r270
  text "GND2" at -2595.51,1969.95 h35
  text "CS1#" at -210.51,1954.95 h35
  text "IO3" at -655.51,1949.95 h35
  text "IO2" at -560.51,1949.95 h35
  text "IO1" at -465.51,1949.95 h35
  text "IO0" at -355.51,1949.95 h35
  text "CLK1" at -40.51,1949.95 h35
  text "VCC" at -2954.92,1906.35 h40 r270
  text "VCCIO_EXIT" at -2210.51,1899.95 h35
  text "J15" at -2802.5,1894.99 h35
  text "INT2#" at -868.43,1882.04 h35
  text "INT1#" at -1105.1,1807.48 h35
  text "IO7" at -1094.94,1734.95 h35
  text "IO6" at -999.94,1734.95 h35
  text "IO5" at -894.94,1734.95 h35
  text "IO4" at -784.94,1734.95 h35
  text "R24" at -1743.51,1711.04 h35 r270
  text "CS2#" at -220.51,1654.95 h35
  text "CLK2" at -30.51,1654.95 h35
  text "VCCIO_1V8" at -10.51,1569.95 h35
  text "JP6" at -340.51,1389.95 h35
  text "+5V" at -195.51,1359.95 h35
  text "EN" at -240.51,1304.95 h35
  text "PS_POR_B" at -45.51,1254.95 h35
  text "VCC_EXT" at -2069.85,1152.32 h35
  text "VCC_3V3" at -15.51,1124.95 h35
  text "JP5" at -360.51,1019.95 h35
  text "PS_POR_B" at -66.45,959.95 h35 r90
  text "+5V" at -328.29,939.95 h35
  text "EN" at -160.51,939.95 h35 r90
  text "JP8" at -2560.51,729.95 h35
  text "GND3" at -2830.51,714.95 h35
  text "JP7" at -2213.01,424.95 h35
  text "PS_POR_B" at -2720.51,419.95 h35
  text "GND4" at -30.51,364.95 h35
  text "VCCIO_EXIT" at -2106.56,311.64 h35
  text "VCCIO" at -2404.56,309.97 h35
  text "VCC" at -2520.51,204.95 h35
  text "RESET#" at -2475.51,134.95 h35
  text "QDS11249_AVL_96BGA_XILINX (V0.9) GEN3" at -930.23,76.04 h30
  text "VCCIO" at -2490.51,64.95 h35
  text "BOTTOM SILKSCREEN" at 2142.32,-48.54 h65
Top Paste:
  text "TOP SOLDER PAST" at 818.9,103.46 h65
Bottom Paste:
  text "BOTTOM SOLDER PAST" at 2142.32,105.46 h65
Top Solder:
  text "TOP SOLDERMASK" at 818.9,-202.54 h65
Bottom Solder:
  text "BOTTOM SOLDERMASK" at 2142.32,-203.54 h65
BRD OUTLINE:
  lines w5: -3000.06,2525.37 -3000.06,2625.37 ; 0,0 100,0
  lines w10: 704.84,-89.05 3454.84,-89.05 ; 704.84,60.95 3454.84,60.95 ; 704.84,210.95 3454.84,210.95 ; 704.84,360.95 3454.84,360.95 ; 704.84,510.95 3454.84,510.95 ; 704.84,660.95 3454.84,660.95 ; 704.84,810.95 3454.84,810.95 ; 704.84,960.95 3454.84,960.95 ; 704.84,1110.95 3454.84,1110.95 ; 704.84,1386.21 3454.84,1386.21 ; 704.84,1561.21 3454.84,1561.21 ; 704.84,1686.21 3454.84,1686.21 ; 704.84,1811.21 3454.84,1811.21 ; 704.84,1936.21 3454.84,1936.21 ; 704.84,2061.21 3454.84,2061.21 ; 704.84,2186.21 3454.84,2186.21 ; 704.84,2311.21 3454.84,2311.21 ; 704.84,2436.21 3454.84,2436.21 ; 704.84,2686.21 3454.84,2686.21 ; 1455.03,1436.21 1455.03,2686.21 ; 2079.84,-239.05 2079.84,1110.95 ; 3454.84,-238.87 704.84,-238.87 ; 704.84,-238.87 3455.17,-238.87 3455.17,-1168.88 704.84,-1168.88 704.84,-238.87 ; 704.84,1436.21 704.84,3836.21 3454.84,3836.21 3454.84,1436.21 ; 704.84,1436.21 3454.84,1436.21 ; 704.84,1436.21 704.84,-239.05 3454.84,-239.05 3454.84,1436.21 ; -3000.02,0 -3000.02,2525.22 0,2525.22 0,-0.01 -3000.02,-0.01
  text "Title:" at 1076.76,2539.62 h75
  text "96BGA_XILINX REV.B" at 1582.4,2526.53 h65
  text "Customer:" at 883.27,2349.35 h65
  text "Contact:" at 967.27,2218.35 h65
  text "CUST P/N#:" at 805.27,2094.35 h65
  text "JOB#:" at 1089.37,1850.14 h65
  text "QDS11249_AVL (V0.9) GEN3" at 1582.4,1846.82 h65
  text "ENG./Designer:" at 782.27,1725.35 h65
  text "Scale:" at 1095.27,1597.35 h65
  text "1 TO 1" at 1588.9,1593.14 h65
  text "View:" at 1106.76,1469.62 h65
  text "TOP VIEW" at 1588.9,1468.14 h65
  text "DATE PLOTTED:" at 866.57,1201.89 h65
  text ".Print_Date" at 2193.37,1195.19 h65
  text "PADMASTER" at 818.9,998.3 h65
  text "DRILLMASTER" at 2142.32,998.3 h65
  text "PROPRIETARY NOTICE" at 1212.69,-388.47 h100
  text "THIS DOCUMENT/FILE AND THE TECHNICAL" at 877.35,-517.46 h75
  text "DATA HEREIN DISCLOSED ARE PROPRIETARY" at 881.25,-641.84 h75
  text "TO Q DESIGN AND SHALL NOT BE DUPLICATED" at 858.36,-769.8 h75
  text "USED, RELEASED, OR DISCLOSED IN" at 876.19,-892.36 h75
  text "WHOLE OR IN PART WITHOUT EXPRESSED" at 874.82,-1012.86 h75
  text "WRITTEN PERMISSION." at 881.44,-1133.82 h75
Mechanical:
  lines w0: -3000.02,1725.17 -3000.02,2525.22 -0.02,2525.22 -0.02,1725.17 ; -0.06,1725.22 -3000.02,1725.22 -3000.02,16.13 -3000.02,0 -2961.82,0 -0.02,0 ; -0.02,214.17 -0.02,0 ; -0.02,1725.22 -0.02,0
Mechanical 9:
  lines w10: -1250.02,701.86 -1250.02,1503.42 -1250.02,1975.86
